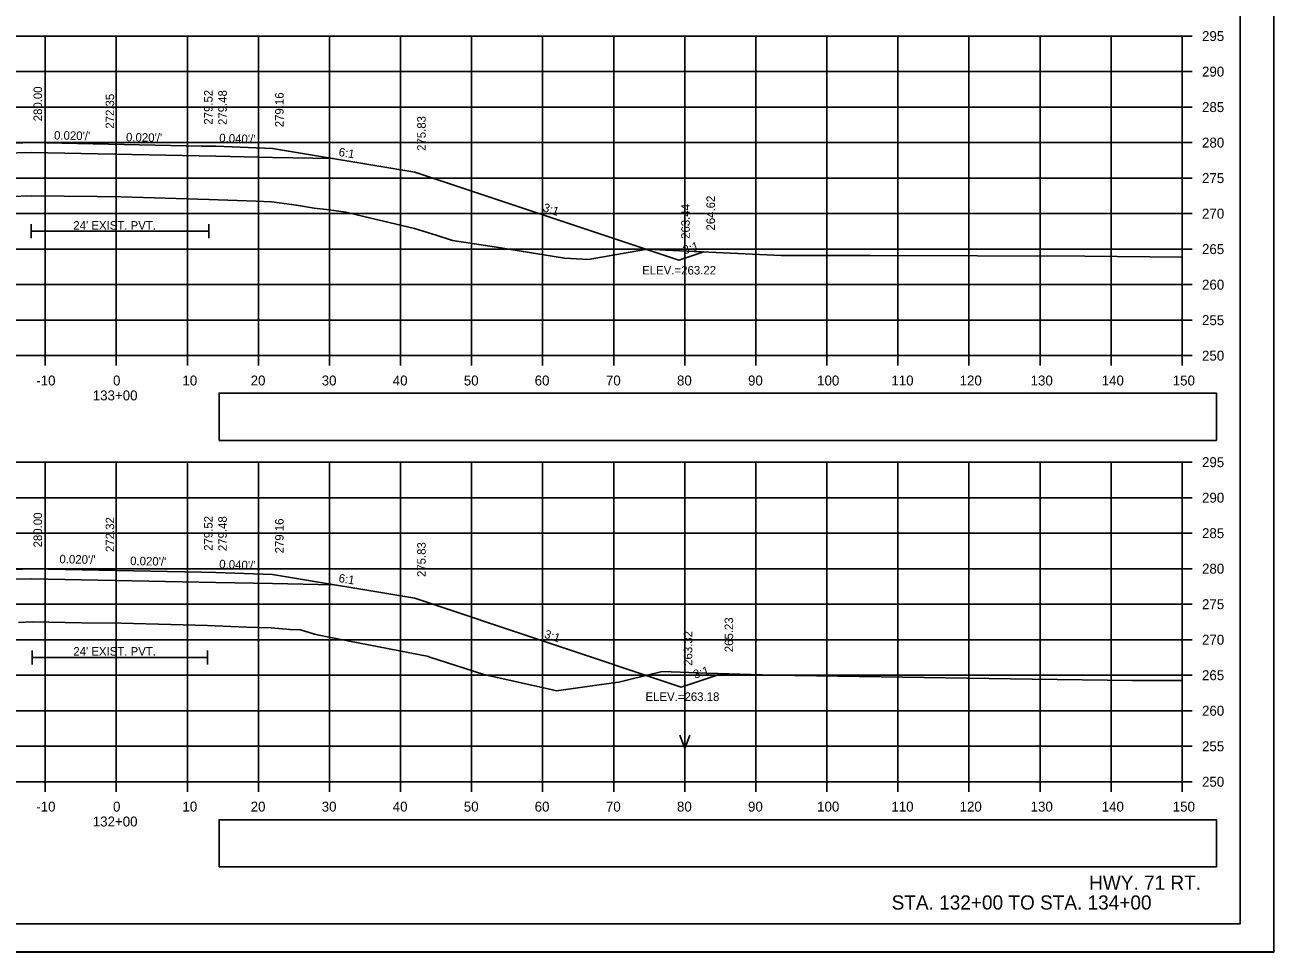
# Model space of a CAD drawing. Extents: x 285 to 4233, y -659 to 3710.
# Drawn here: x 2546.6 to 2722.4, y 1896.2 to 2026.8 of the extents above; entities that cross this region are included whole.
import ezdxf

# ---------------------------------------------------------------- set-up
doc = ezdxf.new("R2010")
doc.units = 0
for name, color, linetype in [('R_Alt Surface', 7, 'Continuous'), ('R_Axis', 7, 'Continuous'), ('R_Axis Annot', 7, 'Continuous'), ('R_Border', 7, 'Continuous'), ('R_Draft', 7, 'Continuous'), ('R_Exist Surface', 7, 'Continuous'), ('R_Fin Surface', 7, 'Continuous'), ('R_Grid', 7, 'Continuous'), ('R_No Plot', 7, 'Continuous'), ('R_Water', 7, 'Continuous'), ('R_Water Annot', 7, 'Continuous'), ('R_Xsect Elev', 7, 'Continuous'), ('R_Xsect Slope', 7, 'Continuous')]:
    doc.layers.add(name, color=color, linetype=linetype)

msp = doc.modelspace()

# ---------------------------------------------------------------- linework, layer by layer
at = {"layer": 'R_Alt Surface'}
for points in [[(2532.66, 2008.48), (2541.5, 2008.66), (2547.5, 2008.78), (2547.5, 2008.78), (2573.5, 2008.26), (2581.5, 2008.1), (2590.07, 2007.93)], [(2547.54, 1998.71), (2547.54, 1996.71)], [(2572.51, 1998.71), (2572.51, 1996.71)], [(2547.54, 1997.71), (2572.51, 1997.71)], [(2532.66, 1948.48), (2541.5, 1948.66), (2547.5, 1948.78), (2547.5, 1948.78), (2573.5, 1948.26), (2581.5, 1948.1), (2590.07, 1947.93)], [(2547.67, 1938.69), (2547.67, 1936.69)], [(2547.67, 1937.69), (2572.34, 1937.69)], [(2572.34, 1938.69), (2572.34, 1936.69)]]:
    msp.add_lwpolyline(points, dxfattribs=at)
at = {"layer": 'R_Axis'}
for p, q in [((2709.5, 1980.19), (2709.5, 2025.19)), ((2710.9, 2025.19), (2709.5, 2025.19)), ((2710.9, 2020.19), (2709.5, 2020.19)), ((2710.9, 2015.19), (2709.5, 2015.19)), ((2710.9, 2010.19), (2709.5, 2010.19)), ((2710.9, 2005.19), (2709.5, 2005.19)), ((2710.9, 2000.19), (2709.5, 2000.19)), ((2710.9, 1995.19), (2709.5, 1995.19)), ((2710.9, 1990.19), (2709.5, 1990.19)), ((2710.9, 1985.19), (2709.5, 1985.19)), ((2409.5, 1980.19), (2709.5, 1980.19)), ((2549.5, 1978.79), (2549.5, 1980.19)), ((2559.5, 1978.79), (2559.5, 1980.19)), ((2569.5, 1978.79), (2569.5, 1980.19)), ((2579.5, 1978.79), (2579.5, 1980.19)), ((2589.5, 1978.79), (2589.5, 1980.19)), ((2599.5, 1978.79), (2599.5, 1980.19)), ((2609.5, 1978.79), (2609.5, 1980.19)), ((2619.5, 1978.79), (2619.5, 1980.19)), ((2629.5, 1978.79), (2629.5, 1980.19)), ((2639.5, 1978.79), (2639.5, 1980.19)), ((2649.5, 1978.79), (2649.5, 1980.19)), ((2659.5, 1978.79), (2659.5, 1980.19)), ((2669.5, 1978.79), (2669.5, 1980.19)), ((2679.5, 1978.79), (2679.5, 1980.19)), ((2689.5, 1978.79), (2689.5, 1980.19)), ((2699.5, 1978.79), (2699.5, 1980.19)), ((2709.5, 1978.79), (2709.5, 1980.19)), ((2710.9, 1980.19), (2709.5, 1980.19)), ((2709.5, 1920.19), (2709.5, 1965.19)), ((2710.9, 1965.19), (2709.5, 1965.19)), ((2710.9, 1960.19), (2709.5, 1960.19)), ((2710.9, 1955.19), (2709.5, 1955.19)), ((2710.9, 1950.19), (2709.5, 1950.19)), ((2710.9, 1945.19), (2709.5, 1945.19)), ((2710.9, 1940.19), (2709.5, 1940.19)), ((2710.9, 1935.19), (2709.5, 1935.19)), ((2710.9, 1930.19), (2709.5, 1930.19)), ((2710.9, 1925.19), (2709.5, 1925.19)), ((2409.5, 1920.19), (2709.5, 1920.19)), ((2549.5, 1918.79), (2549.5, 1920.19)), ((2559.5, 1918.79), (2559.5, 1920.19)), ((2569.5, 1918.79), (2569.5, 1920.19)), ((2579.5, 1918.79), (2579.5, 1920.19)), ((2589.5, 1918.79), (2589.5, 1920.19)), ((2599.5, 1918.79), (2599.5, 1920.19)), ((2609.5, 1918.79), (2609.5, 1920.19)), ((2619.5, 1918.79), (2619.5, 1920.19)), ((2629.5, 1918.79), (2629.5, 1920.19)), ((2639.5, 1918.79), (2639.5, 1920.19)), ((2649.5, 1918.79), (2649.5, 1920.19)), ((2659.5, 1918.79), (2659.5, 1920.19)), ((2669.5, 1918.79), (2669.5, 1920.19)), ((2679.5, 1918.79), (2679.5, 1920.19)), ((2689.5, 1918.79), (2689.5, 1920.19)), ((2699.5, 1918.79), (2699.5, 1920.19)), ((2709.5, 1918.79), (2709.5, 1920.19)), ((2710.9, 1920.19), (2709.5, 1920.19))]:
    msp.add_line(p, q, dxfattribs=at)
at = {"layer": 'R_Axis Annot'}
for points in [[(2573.96, 1968.26), (2714.32, 1968.26), (2714.32, 1974.92), (2573.96, 1974.92)], [(2573.96, 1908.2), (2714.32, 1908.2), (2714.32, 1914.85), (2573.96, 1914.85)]]:
    msp.add_lwpolyline(points, close=True, dxfattribs=at)
at = {"layer": 'R_Border'}
for q in [(2717.68, 2105.65), (2401.5, 1900.19)]:
    msp.add_line((2717.68, 1900.19), q, dxfattribs=at)
at = {"layer": 'R_Exist Surface'}
for points in [[(2544.64, 2002.59), (2547.54, 2002.71), (2556.83, 2002.58), (2560.12, 2002.54), (2563.31, 2002.45), (2572.51, 2002.19), (2579.19, 2001.95), (2581.34, 2001.87), (2583.49, 2001.56), (2584.18, 2001.47), (2585.15, 2001.31), (2587.35, 2000.96), (2589.1, 2000.77), (2591.79, 2000.41), (2594.34, 1999.79), (2601.46, 1998.1), (2604.53, 1997.15), (2606.8, 1996.42), (2613.01, 1995.46), (2622.58, 1993.91), (2625.11, 1993.77), (2625.91, 1993.75), (2633.69, 1995.07), (2634.44, 1995.19), (2636.78, 1995.06), (2653.09, 1994.31), (2665.59, 1994.3), (2695.82, 1994.21), (2709.5, 1994.07)], [(2545.76, 1942.6), (2547.67, 1942.69), (2554.64, 1942.59), (2560.19, 1942.5), (2567.18, 1942.31), (2572.34, 1942.17), (2577.81, 1941.97), (2581.3, 1941.84), (2583.98, 1941.64), (2585.44, 1941.57), (2587.4, 1940.99), (2588.04, 1940.81), (2589.41, 1940.56), (2603.47, 1937.81), (2603.48, 1937.8), (2611.22, 1935.3), (2620.89, 1933.12), (2621.46, 1933.01), (2629.78, 1934.17), (2630.21, 1934.22), (2631.53, 1934.55), (2636.33, 1935.73), (2642.6, 1935.49), (2651.93, 1935.2), (2688.38, 1934.64), (2702.51, 1934.46), (2709.5, 1934.43)]]:
    msp.add_lwpolyline(points, dxfattribs=at)
at = {"layer": 'R_Fin Surface'}
for points in [[(2486.16, 2003.13), (2497.59, 1999.32), (2517.5, 2005.95), (2541.5, 2009.95), (2547.5, 2010.19), (2571.5, 2009.71), (2573.5, 2009.67), (2581.5, 2009.35), (2601.5, 2006.02), (2638.66, 1993.63), (2642.2, 1994.81)], [(2475.01, 1943.09), (2491.96, 1937.44), (2517.5, 1945.95), (2541.5, 1949.95), (2547.5, 1950.19), (2571.5, 1949.71), (2573.5, 1949.67), (2581.5, 1949.35), (2601.5, 1946.02), (2639.02, 1933.51), (2644.76, 1935.43)]]:
    msp.add_lwpolyline(points, dxfattribs=at)
at = {"layer": 'R_Grid'}
for p, q in [((2409.5, 2025.19), (2709.5, 2025.19)), ((2549.5, 1980.19), (2549.5, 2025.19)), ((2559.5, 1980.19), (2559.5, 2025.19)), ((2569.5, 1980.19), (2569.5, 2025.19)), ((2579.5, 1980.19), (2579.5, 2025.19)), ((2589.5, 1980.19), (2589.5, 2025.19)), ((2599.5, 1980.19), (2599.5, 2025.19)), ((2609.5, 1980.19), (2609.5, 2025.19)), ((2619.5, 1980.19), (2619.5, 2025.19)), ((2629.5, 1980.19), (2629.5, 2025.19)), ((2639.5, 1980.19), (2639.5, 2025.19)), ((2649.5, 1980.19), (2649.5, 2025.19)), ((2659.5, 1980.19), (2659.5, 2025.19)), ((2669.5, 1980.19), (2669.5, 2025.19)), ((2679.5, 1980.19), (2679.5, 2025.19)), ((2689.5, 1980.19), (2689.5, 2025.19)), ((2699.5, 1980.19), (2699.5, 2025.19)), ((2709.5, 1980.19), (2709.5, 2025.19)), ((2409.5, 2020.19), (2709.5, 2020.19)), ((2409.5, 2015.19), (2709.5, 2015.19)), ((2409.5, 2010.19), (2709.5, 2010.19)), ((2409.5, 2005.19), (2709.5, 2005.19)), ((2409.5, 2000.19), (2709.5, 2000.19)), ((2409.5, 1995.19), (2709.5, 1995.19)), ((2409.5, 1990.19), (2709.5, 1990.19)), ((2409.5, 1985.19), (2709.5, 1985.19)), ((2409.5, 1980.19), (2709.5, 1980.19)), ((2409.5, 1965.19), (2709.5, 1965.19)), ((2549.5, 1920.19), (2549.5, 1965.19)), ((2559.5, 1920.19), (2559.5, 1965.19)), ((2569.5, 1920.19), (2569.5, 1965.19)), ((2579.5, 1920.19), (2579.5, 1965.19)), ((2589.5, 1920.19), (2589.5, 1965.19)), ((2599.5, 1920.19), (2599.5, 1965.19)), ((2609.5, 1920.19), (2609.5, 1965.19)), ((2619.5, 1920.19), (2619.5, 1965.19)), ((2629.5, 1920.19), (2629.5, 1965.19)), ((2639.5, 1920.19), (2639.5, 1965.19)), ((2649.5, 1920.19), (2649.5, 1965.19)), ((2659.5, 1920.19), (2659.5, 1965.19)), ((2669.5, 1920.19), (2669.5, 1965.19)), ((2679.5, 1920.19), (2679.5, 1965.19)), ((2689.5, 1920.19), (2689.5, 1965.19)), ((2699.5, 1920.19), (2699.5, 1965.19)), ((2709.5, 1920.19), (2709.5, 1965.19)), ((2409.5, 1960.19), (2709.5, 1960.19)), ((2409.5, 1955.19), (2709.5, 1955.19)), ((2409.5, 1950.19), (2709.5, 1950.19)), ((2409.5, 1945.19), (2709.5, 1945.19)), ((2409.5, 1940.19), (2709.5, 1940.19)), ((2409.5, 1935.19), (2709.5, 1935.19)), ((2409.5, 1930.19), (2709.5, 1930.19)), ((2409.5, 1925.19), (2709.5, 1925.19)), ((2409.5, 1920.19), (2709.5, 1920.19))]:
    msp.add_line(p, q, dxfattribs=at)
at = {"layer": 'R_No Plot'}
msp.add_line((2389.1, 1896.22), (2722.43, 1896.22), dxfattribs=at)
for points in [[(2389.09, 2109.55), (2722.43, 2109.55), (2722.43, 1896.21), (2389.09, 1896.21)], [(2635.42, 2105.65), (2655.04, 2105.65), (2655.04, 2095.77), (2671.15, 2095.77), (2694.35, 2095.77), (2694.47, 2067.62), (2717.68, 2067.62), (2717.68, 1900.19), (2401.5, 1900.19), (2401.5, 2105.65)]]:
    msp.add_lwpolyline(points, close=True, dxfattribs=at)
at = {"layer": 'R_Water Annot'}
for p, q in [((2639.53, 1931.14), (2639.53, 1924.85)), ((2639.53, 1924.85), (2638.83, 1926.77)), ((2639.53, 1924.85), (2640.23, 1926.77))]:
    msp.add_line(p, q, dxfattribs=at)
at = {"layer": 'R_Xsect Elev'}
for p, q in [((2559.5, 2002.55), (2559.5, 2018.82)), ((2559.5, 1942.51), (2559.5, 1958.36))]:
    msp.add_line(p, q, dxfattribs=at)

# ---------------------------------------------------------------- texts
at = {"layer": 'R_Axis Annot'}
for s, p in [('295', (2712.3, 2024.49)), ('290', (2712.3, 2019.49)), ('285', (2712.3, 2014.49)), ('280', (2712.3, 2009.49)), ('275', (2712.3, 2004.49)), ('270', (2712.3, 1999.49)), ('265', (2712.3, 1994.49)), ('260', (2712.3, 1989.49)), ('255', (2712.3, 1984.49)), ('250', (2712.3, 1979.49)), ('-10', (2548.24, 1975.99)), ('0', (2559.04, 1975.99)), ('10', (2568.81, 1975.99)), ('20', (2578.41, 1975.99)), ('30', (2588.41, 1975.99)), ('40', (2598.41, 1975.99)), ('50', (2608.41, 1975.99)), ('60', (2618.38, 1975.99)), ('70', (2628.41, 1975.99)), ('80', (2638.41, 1975.99)), ('90', (2648.41, 1975.99)), ('100', (2658.13, 1975.99)), ('110', (2668.58, 1975.99)), ('120', (2678.18, 1975.99)), ('130', (2688.18, 1975.99)), ('140', (2698.18, 1975.99)), ('150', (2708.18, 1975.99)), ('133+00', (2556.19, 1973.89)), ('295', (2712.3, 1964.49)), ('290', (2712.3, 1959.49)), ('285', (2712.3, 1954.49)), ('280', (2712.3, 1949.49)), ('275', (2712.3, 1944.49)), ('270', (2712.3, 1939.49)), ('265', (2712.3, 1934.49)), ('260', (2712.3, 1929.49)), ('255', (2712.3, 1924.49)), ('250', (2712.3, 1919.49)), ('-10', (2548.24, 1915.99)), ('0', (2559.04, 1915.99)), ('10', (2568.81, 1915.99)), ('20', (2578.41, 1915.99)), ('30', (2588.41, 1915.99)), ('40', (2598.41, 1915.99)), ('50', (2608.41, 1915.99)), ('60', (2618.38, 1915.99)), ('70', (2628.41, 1915.99)), ('80', (2638.41, 1915.99)), ('90', (2648.41, 1915.99)), ('100', (2658.13, 1915.99)), ('110', (2668.58, 1915.99)), ('120', (2678.18, 1915.99)), ('130', (2688.18, 1915.99)), ('140', (2698.18, 1915.99)), ('150', (2708.18, 1915.99)), ('132+00', (2556.19, 1913.89))]:
    msp.add_text(s, height=1.4, dxfattribs=at).set_placement(p)
at = {"layer": 'R_Draft'}
for s, p in [('HWY. 71 RT. ', (2696.41, 1904.98)), ('STA. 132+00 TO STA. 134+00', (2668.62, 1902.19))]:
    msp.add_text(s, height=2, dxfattribs=at).set_placement(p)
at = {"layer": 'R_Water'}
for p in [(2553.45, 1997.93), (2553.45, 1937.95)]:
    msp.add_text("24' EXIST. PVT.", height=1.2, dxfattribs=at).set_placement(p)
at = {"layer": 'R_Xsect Elev'}
for s, p in [('280.00', (2549.05, 2013.19)), ('272.35', (2559.2, 2012.15)), ('279.52', (2573.05, 2012.71)), ('279.48', (2575.05, 2012.67)), ('279.16', (2583.05, 2012.35)), ('275.83', (2603.05, 2009.02)), ('264.62', (2643.75, 1997.81)), ('263.44', (2640.21, 1996.63)), ('280.00', (2549.05, 1953.19)), ('272.32', (2559.2, 1952.54)), ('279.52', (2573.05, 1952.71)), ('279.48', (2575.05, 1952.67)), ('279.16', (2583.05, 1952.35)), ('275.83', (2603.05, 1949.02)), ('265.23', (2646.31, 1938.43)), ('263.32', (2640.57, 1936.51))]:
    msp.add_text(s, height=1.2, rotation=90, dxfattribs=at).set_placement(p)
for s, p in [('ELEV.=263.22', (2633.51, 1991.62)), ('ELEV.=263.18', (2633.98, 1931.57))]:
    msp.add_text(s, height=1.2, dxfattribs=at).set_placement(p)
at = {"layer": 'R_Xsect Slope'}
for s, rotation, p in [("0.020'/'", 358.8542, (2550.73, 2010.63)), ("0.020'/'", 358.8542, (2560.86, 2010.37)), ("0.040'/'", 357.7094, (2573.97, 2010.26)), ('6:1', 350.5377, (2590.73, 2008.32)), ('3:1', 341.5651, (2619.45, 2000.56)), ('3:1', 18.4349, (2639.48, 1994.44)), ("0.020'/'", 358.8542, (2551.49, 1950.96)), ("0.020'/'", 358.8542, (2561.44, 1950.7)), ("0.040'/'", 357.7094, (2573.97, 1950.26)), ('6:1', 350.5377, (2590.73, 1948.32)), ('3:1', 341.5651, (2619.63, 1940.5)), ('3:1', 18.4349, (2640.94, 1934.68))]:
    msp.add_text(s, height=1.2, rotation=rotation, dxfattribs=at).set_placement(p)

doc.saveas('drawing.dxf')
